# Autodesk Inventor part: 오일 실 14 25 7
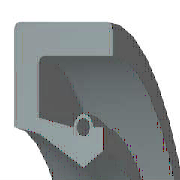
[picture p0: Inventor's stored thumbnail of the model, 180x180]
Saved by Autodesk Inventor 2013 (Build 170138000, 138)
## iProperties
Created: 2012-02
Part Number: 오일 실 14 25 7
Material: 고무
Description: 오일 실 - 스프링 장착, 금속 케이스 SM
Document SubType Name: Modeling
Standard: JIS B 2402
Designer: mdu-01
Standards Organization: JIS
Language: ko-KR
Size Designation: 14 25 7 A
Categories: <MemberInstance><Categories><Category DisplayName="샤프트 부품" InternalName="7f7aeb1f-a693-4053-b835-cee3144e0d98" Mnemonic="SHFT"><Category DisplayName="실링" Intern
Density: 0.93 g/cm^3
IsCustomPart: 1
Author: mdu-01
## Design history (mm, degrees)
body "Solid1"
revolve "회전1" stored, may be unused: angle "d33" = 360 deg
fillet "모깎기1" dims "d34" = 0.35 (= 0.05 x b)
chamfer "모따기1" distance "d35" = 0.7 (= 0.1 x b); stored, may be unused: second distance "d36" = 0.35 (= 0.05 x b), angle "d41" = 45 deg
sketch "스케치2"
  geometry: L1 (8.336, -5.158)-(8.853, -7); L2 (7.786, -4.55)-(8.336, -5.158); L3 (7, -1.75)-(7.786, -4.55); L4 (7.733, -0.875)-(7, -1.75); L5 (8.963, -0.875)-(7.733, -0.875); L6 (8.963, -1.575)-(8.963, -0.875); L7 (8.963, -5.25)-(8.963, -2.975); L8 (10.3, -5.25)-(8.963, -5.25); L9 (11.4, -1.75)-(10.3, -5.25); L10 (11.4, 0)-(11.4, -1.75); L11 (12.5, 0)-(11.4, 0); L12 (12.5, -7)-(12.5, 0); L13 (8.853, -7)-(12.5, -7); L14 (0, -9.6)-(0, 1.6) reference; L15 (28, 0)-(14, 0) reference; A1 r 0.7 centre (8.963, -2.275) between (8.963, -2.975) and (8.963, -1.575)
  constraints: 26 end point, 4 horizontal, 4 vertical, 2 point on circle, 1 centre point, 1 collinear, 1 parallel
  dimensions: "d2" = 7 distance of L12.start L11.start (= b); "d4" = 0.875 vertical distance of L10.start L5.start (= 0.125 x b); "d6" = 1.1 distance of L11.start L10.start (= 0.1 x dd - 0.1 x Diam); "d8" = 1.75 distance of L10.start L9.start (= 0.25 x b); "d10" = 1.75 vertical distance of L8.start L1.end (= 0.25 x b); "d12" = 1.1 horizontal distance of L9.start L8.start (= 0.1 x dd - 0.1 x Diam); "d14" = 0.7 radius of A1 (= 0.1 x b); "d16" = 0 horizontal distance of A1.centre L7.end; "d18" = 0.7 distance of L6.start L5.start (= 0.1 x b); "d20" = 0.73333 horizontal distance of L4.start L3.start (= 0.0666667 x dd - 0.0666667 x Diam); "d22" = 0.11 horizontal distance of L7.start L1.end (= 0.01 x dd - 0.01 x Diam); "d24" = 0.875 vertical distance of L4.start L3.start (= 0.125 x b); "d26" = 2.8 vertical distance of L3.start L2.start (= 0.4 x b); "d28" = 0.78571 horizontal distance of L3.start L2.start (= 0.0714286 x dd - 0.0714286 x Diam); "d30" = 1.84211 vertical distance of L1.start L1.end (= 0.263158 x b); "d32" = 0.55 horizontal distance of L2.start L1.start (= 0.05 x dd - 0.05 x Diam); "d37" = 0 distance between parallel lines of L15 L11; "d38" = 12.5 distance between parallel lines of L14 L12 (= 0.5 x dd); "d39" = 7 distance from line of L14 L3.start (= 0.5 x Diam)
other parameters: "dd" = 25 [user parameter; used in 7 equation terms], "Diam" = 14 [user parameter; used in 7 equation terms], "b" = 7 [user parameter; used in 12 equation terms], "d1" = 8 (derived), "d3" = 1 (derived), "d5" = 2 (derived), "d7" = 2 (derived), "d9" = 2 (derived), "d11" = 2 (derived), "d13" = 0.8 (derived), "d15" = 0 (derived), "d17" = 0.8 (derived), "d19" = 1.33333 (derived), "d21" = 0.2 (derived), "d23" = 1 (derived), "d25" = 3.2 (derived), "d27" = 1.42857 (derived), "d29" = 2.10526 (derived), "d31" = 1 (derived), "d40" = 0
